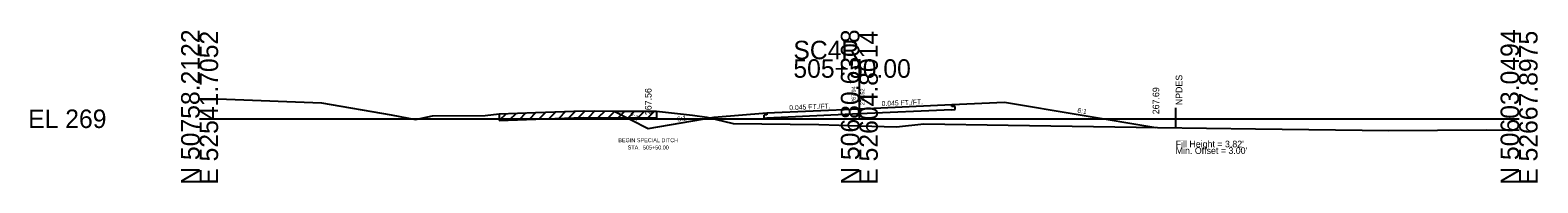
# Model space of a CAD drawing. Extents: x 7498 to 13027, y 90095 to 109625.
# Drawn here: x 8498.3 to 8726.8, y 95595.5 to 95618.6 of the extents above; entities that cross this region are included whole.
import ezdxf

# ---------------------------------------------------------------- set-up
doc = ezdxf.new("R2010")
doc.units = 0
for name, color, linetype in [('Level 10', 7, 'Continuous'), ('Level 11', 7, 'Continuous'), ('Level 12', 7, 'Continuous'), ('Level 32', 7, 'Continuous'), ('Level 33', 7, 'Continuous'), ('Level 50', 7, 'Continuous'), ('Level 55', 7, 'Continuous'), ('Level 59', 7, 'Continuous'), ('Level 6', 7, 'Continuous'), ('Level 60', 7, 'Continuous'), ('Level 61', 7, 'Continuous'), ('Level 63', 7, 'Continuous'), ('Level 7', 7, 'Continuous')]:
    doc.layers.add(name, color=color, linetype=linetype)

msp = doc.modelspace()

# ---------------------------------------------------------------- linework, layer by layer
at = {"layer": 'Level 11'}
for p, q in [((8637.99, 95607.01), (8637.99, 95607.31)), ((8638.49, 95607.03), (8637.99, 95607.01)), ((8637.99, 95606.53), (8638.49, 95606.55)), ((8638.49, 95606.55), (8638.49, 95607.03)), ((8609.99, 95605.75), (8609.49, 95605.72)), ((8609.49, 95605.72), (8609.49, 95605.24)), ((8609.49, 95605.24), (8609.99, 95605.27)), ((8609.99, 95606.05), (8609.99, 95605.75))]:
    msp.add_line(p, q, dxfattribs=at)
at = {"layer": 'Level 12'}
for p, q in [((8637.99, 95606.53), (8623.99, 95605.9)), ((8623.99, 95605.9), (8609.99, 95605.27))]:
    msp.add_line(p, q, dxfattribs=at)
at = {"layer": 'Level 55'}
msp.add_line((8671.94, 95603.84), (8671.94, 95606.84), dxfattribs=at)
at = {"layer": 'Level 59'}
for p, q in [((8609.99, 95606.05), (8623.99, 95606.68)), ((8623.99, 95606.68), (8637.99, 95607.31))]:
    msp.add_line(p, q, dxfattribs=at)
at = {"layer": 'Level 6'}
for p, q in [((8637.99, 95607.31), (8645.99, 95607.67)), ((8601.99, 95605.38), (8609.99, 95606.05))]:
    msp.add_line(p, q, dxfattribs=at)
at = {"layer": 'Level 60'}
for p, q in [((8523.99, 95608.16), (8528.05, 95608.13)), ((8528.05, 95608.13), (8542.45, 95607.55)), ((8542.45, 95607.55), (8553.01, 95605.75)), ((8574.96, 95606.09), (8582.17, 95606.35)), ((8582.17, 95606.35), (8587.24, 95606.31)), ((8587.24, 95606.31), (8593.23, 95606.29)), ((8593.23, 95606.29), (8598.7, 95605.69)), ((8553.01, 95605.75), (8556.7, 95605.06)), ((8556.7, 95605.06), (8559.31, 95605.59)), ((8559.31, 95605.59), (8567.27, 95605.67)), ((8567.27, 95605.67), (8569.38, 95605.89)), ((8569.38, 95605.89), (8574.96, 95606.09)), ((8598.7, 95605.69), (8600.86, 95605.41)), ((8600.86, 95605.41), (8604.85, 95604.46)), ((8604.85, 95604.46), (8617.87, 95604.29)), ((8617.87, 95604.29), (8623.99, 95604.1)), ((8623.99, 95604.1), (8629.64, 95603.93)), ((8629.64, 95603.93), (8633.77, 95604.4)), ((8633.77, 95604.4), (8646.56, 95604.19)), ((8646.56, 95604.19), (8669.2, 95603.84)), ((8669.2, 95603.84), (8684.05, 95603.64)), ((8684.05, 95603.64), (8704.23, 95603.4)), ((8704.23, 95603.4), (8718.99, 95603.46)), ((8718.99, 95603.46), (8723.99, 95603.42))]:
    msp.add_line(p, q, dxfattribs=at)
at = {"layer": 'Level 61'}
for p, q in [((8576.46, 95606.15), (8575.42, 95605.11)), ((8577.96, 95606.2), (8576.92, 95605.16)), ((8579.46, 95606.25), (8578.42, 95605.22)), ((8580.96, 95606.31), (8579.92, 95605.27)), ((8582.45, 95606.35), (8581.42, 95605.33)), ((8583.91, 95606.34), (8582.92, 95605.35)), ((8585.42, 95606.32), (8584.42, 95605.33)), ((8586.92, 95606.31), (8585.92, 95605.32)), ((8588.42, 95606.3), (8587.43, 95605.31)), ((8589.92, 95606.3), (8588.93, 95605.3)), ((8591.42, 95606.29), (8590.43, 95605.3)), ((8592.93, 95606.29), (8591.93, 95605.29)), ((8593.27, 95605.28), (8593.27, 95606.28)), ((8570.45, 95605.93), (8569.41, 95604.89)), ((8569.41, 95605.89), (8569.41, 95604.89)), ((8569.41, 95604.89), (8574.96, 95605.09)), ((8571.95, 95605.98), (8570.91, 95604.94)), ((8573.46, 95606.04), (8572.42, 95605)), ((8574.96, 95606.09), (8573.92, 95605.05)), ((8574.96, 95605.09), (8582.17, 95605.35)), ((8582.17, 95605.35), (8587.24, 95605.31)), ((8587.24, 95605.31), (8593.23, 95605.29)), ((8593.23, 95605.29), (8593.27, 95605.28))]:
    msp.add_line(p, q, dxfattribs=at)
at = {"layer": 'Level 63'}
for p, q in [((8623.99, 95605.16), (8623.99, 95614.17)), ((8523.99, 95605.16), (8623.99, 95605.16)), ((8623.99, 95605.16), (8723.99, 95605.16))]:
    msp.add_line(p, q, dxfattribs=at)
at = {"layer": 'Level 7'}
for p, q in [((8586.8, 95606.31), (8591.99, 95603.71)), ((8645.99, 95607.67), (8668.94, 95603.84)), ((8591.99, 95603.71), (8601.99, 95605.38))]:
    msp.add_line(p, q, dxfattribs=at)

# ---------------------------------------------------------------- texts
at = {"layer": 'Level 10'}
msp.add_text('267.94', height=0.6, rotation=90, dxfattribs=at).set_placement((8623.43, 95607.54))
at = {"layer": 'Level 32'}
for s, rotation, p in [('0.045 FT./FT.', 2.5766, (8613.38, 95606.45)), ('0.045 FT./FT.', 2.5766, (8627.38, 95607.08)), ('6:1', 350.5377, (8656.99, 95606.09)), ('2:1', 333.435, (8589, 95605.49)), ('6:1', 9.4623, (8596.43, 95604.71))]:
    msp.add_text(s, height=0.75, rotation=rotation, dxfattribs=at).set_placement(p)
for s, p in [('BEGIN SPECIAL DITCH', (8587.45, 95601.61)), ('STA.  505+50.00', (8588.87, 95600.51))]:
    msp.add_text(s, height=0.6, dxfattribs=at).set_placement(p)
at = {"layer": 'Level 33'}
for s, p in [('267.56', (8592.49, 95605.71)), ('267.69', (8669.44, 95605.84))]:
    msp.add_text(s, height=1, rotation=90, dxfattribs=at).set_placement(p)
at = {"layer": 'Level 50'}
msp.add_text(' NPDES', height=1, rotation=90, dxfattribs=at).set_placement((8672.94, 95606.84))
for s, p in [("Fill Height = 3.82' ", (8671.94, 95600.84)), ("Min. Offset = 3.00' ", (8671.94, 95599.84))]:
    msp.add_text(s, height=1, dxfattribs=at).set_placement(p)
at = {"layer": 'Level 59'}
msp.add_text(' 270.52', height=0.6, rotation=90, dxfattribs=at).set_placement((8624.75, 95606.98))
at = {"layer": 'Level 63'}
for s, p in [('N 50758.2122', (8523.99, 95595.16)), ('E 52541.7052', (8526.79, 95595.16)), ('N 50680.6308', (8623.99, 95595.16)), ('E 52604.8014', (8626.79, 95595.16)), ('N 50603.0494', (8723.99, 95595.16)), ('E 52667.8975', (8726.79, 95595.16))]:
    msp.add_text(s, height=2.8, rotation=90, dxfattribs=at).set_placement(p)
for s, p in [('SC4R', (8613.99, 95614.17)), ('505+50.00', (8613.99, 95611.37)), ('EL 269', (8498, 95603.76))]:
    msp.add_text(s, height=2.8, dxfattribs=at).set_placement(p)

doc.saveas('drawing.dxf')
